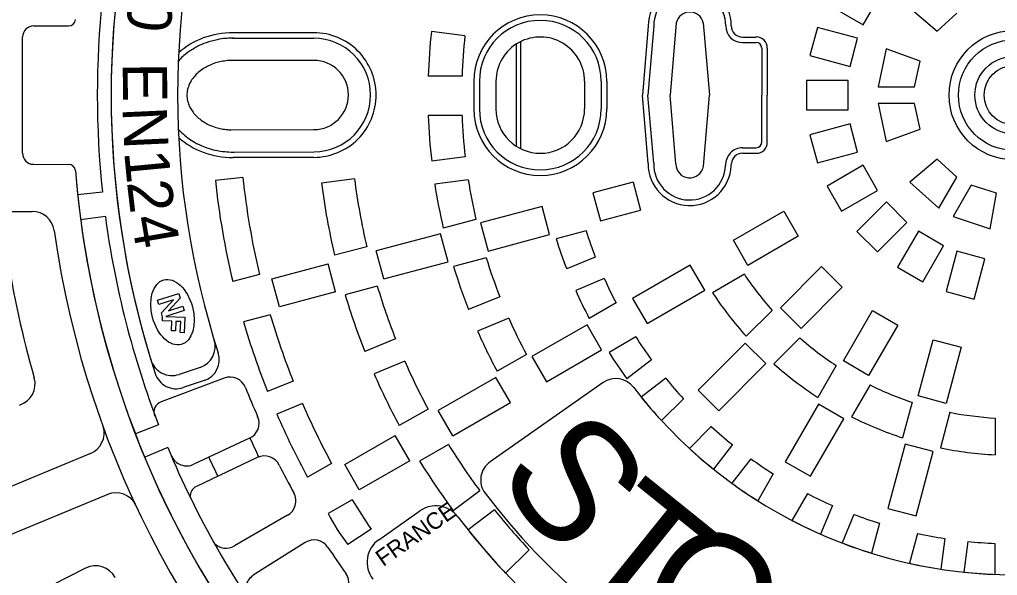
# Model space of a CAD drawing. Extents: x -7.1 to 10, y -5 to 6.
# Drawn here: x -5.508 to -4.588, y 0.27 to 0.793 of the extents above; entities that cross this region are included whole.
import ezdxf

# ---------------------------------------------------------------- set-up
doc = ezdxf.new("R2010")
doc.units = 0
doc.layers.add('Level 1', color=7, linetype='Continuous')

# ---------------------------------------------------------------- blocks, each defined once
blk = doc.blocks.new('CRAN')
at = {"layer": 'Level 1'}
for p, q in [((-3.652, 6.599), (-1.391, 7.083)), ((-3.232, 4.178), (-1.568, 4.4)), ((-1.568, 4.4), (-1.47, 3.52)), ((-3.114, 3.352), (-1.47, 3.52)), ((-2.949, 0.9), (-0.638, 0.965)), ((-2.949, -0.892), (-0.638, -0.957)), ((-3.114, -3.345), (-1.471, -3.52)), ((-1.568, -4.392), (-1.47, -3.512)), ((-3.232, -4.17), (-1.568, -4.392)), ((-3.652, -6.592), (-1.391, -7.076))]:
    blk.add_line(p, q, dxfattribs=at)
for centre, radius, start, end in [((-1.26, 6.472), 0.625, 11.0144, 102.0722), ((-3.521, 5.988), 0.625, 102.0722, 190.9368), ((-34.491, 0.004), 30.918, 8.7409, 10.9368), ((-3.315, 4.797), 0.625, 188.7409, 277.6056), ((-3.048, 2.731), 0.625, 96.0776, 184.9422), ((-34.473, 0.013), 30.918, 2.7463, 4.9422), ((-2.967, 1.524), 0.625, 182.7463, 271.611), ((-0.656, 1.589), 0.625, 271.611, 348.8242), ((-2.967, -1.517), 0.625, 88.389, 177.2537), ((-0.656, -1.582), 0.625, 11.1758, 88.389), ((-34.473, -0.006), 30.918, 355.0578, 357.2537), ((-3.048, -2.723), 0.625, 175.0578, 263.9224), ((-3.315, -4.79), 0.625, 82.3944, 171.2591), ((-34.491, 0.004), 30.918, 349.0632, 351.2591), ((-3.521, -5.981), 0.625, 169.0632, 257.9278), ((-1.26, -6.464), 0.625, 257.9278, 348.9856)]:
    blk.add_arc(centre, radius, start, end, dxfattribs=at)

msp = doc.modelspace()

# ---------------------------------------------------------------- linework, layer by layer
at = {"layer": 'Level 1'}
for p, q in [((-4.71412, 0.78776), (-4.70045, 0.81144)), ((-4.74806, 0.80735), (-4.71412, 0.78776)), ((-4.67027, 0.80377), (-4.64433, 0.78201)), ((-4.64433, 0.78201), (-4.62597, 0.79878)), ((-5.49433, 0.78688), (-5.46154, 0.78688)), ((-4.91624, 0.78688), (-4.92173, 0.72178)), ((-4.91103, 0.78688), (-4.9165, 0.72178)), ((-4.88986, 0.78985), (-4.8956, 0.72178)), ((-4.8645, 0.78985), (-4.85876, 0.72178)), ((-4.75715, 0.78541), (-4.76422, 0.759)), ((-4.7193, 0.77527), (-4.75715, 0.78541)), ((-5.50484, 0.66714), (-5.50475, 0.77647)), ((-5.3072, 0.77531), (-5.23079, 0.77531)), ((-5.23079, 0.78052), (-5.3068, 0.78052)), ((-5.08867, 0.77761), (-5.12018, 0.78176)), ((-4.8277, 0.77646), (-4.81468, 0.77646)), ((-4.72638, 0.74886), (-4.7193, 0.77527)), ((-5.04044, 0.76976), (-5.04044, 0.67446)), ((-5.03653, 0.77038), (-5.03653, 0.67154)), ((-4.8277, 0.77126), (-4.81468, 0.77126)), ((-4.80947, 0.76605), (-4.80947, 0.72178)), ((-4.80426, 0.76605), (-4.80426, 0.72178)), ((-4.69238, 0.76546), (-4.69986, 0.72959)), ((-4.66058, 0.75387), (-4.69238, 0.76546)), ((-5.23079, 0.75448), (-5.3068, 0.75447)), ((-4.76422, 0.759), (-4.72638, 0.74886)), ((-4.66592, 0.72959), (-4.66058, 0.75387)), ((-5.09137, 0.7397), (-5.12316, 0.73977)), ((-5.0803, 0.7348), (-5.0803, 0.70876)), ((-5.0751, 0.7348), (-5.0751, 0.70876)), ((-5.05947, 0.7348), (-5.05947, 0.70876)), ((-4.97614, 0.7348), (-4.97614, 0.70876)), ((-4.96051, 0.7348), (-4.96051, 0.70876)), ((-4.9553, 0.7348), (-4.9553, 0.70876)), ((-4.76732, 0.73545), (-4.76732, 0.70811)), ((-4.72814, 0.73545), (-4.76732, 0.73545)), ((-4.72814, 0.70811), (-4.72814, 0.73545)), ((-4.69986, 0.72959), (-4.66592, 0.72959)), ((-4.91631, 0.65751), (-4.92173, 0.72178)), ((-4.9111, 0.65768), (-4.9165, 0.72178)), ((-4.89027, 0.65718), (-4.8956, 0.72178)), ((-4.86439, 0.65496), (-4.85876, 0.72178)), ((-4.80947, 0.67751), (-4.80947, 0.72178)), ((-4.80426, 0.67751), (-4.80426, 0.72178)), ((-4.66592, 0.71396), (-4.69986, 0.71396)), ((-4.69986, 0.71396), (-4.69238, 0.67809)), ((-4.66058, 0.68968), (-4.66592, 0.71396)), ((-5.09133, 0.70249), (-5.12312, 0.70249)), ((-4.76732, 0.70811), (-4.72814, 0.70811)), ((-4.72638, 0.6947), (-4.76422, 0.68456)), ((-4.7193, 0.66829), (-4.72638, 0.6947)), ((-5.30842, 0.6891), (-5.23068, 0.68937)), ((-4.76422, 0.68456), (-4.75715, 0.65814)), ((-4.69238, 0.67809), (-4.66058, 0.68968)), ((-4.82766, 0.6723), (-4.81468, 0.6723)), ((-5.3072, 0.66825), (-5.23059, 0.66854)), ((-5.23079, 0.66304), (-5.3068, 0.66304)), ((-5.08844, 0.66379), (-5.11994, 0.65964)), ((-4.82766, 0.66709), (-4.81468, 0.66709)), ((-4.75715, 0.65814), (-4.7193, 0.66829)), ((-5.49443, 0.65672), (-5.46153, 0.65668)), ((-4.83822, 0.65541), (-4.83804, 0.65755)), ((-4.71412, 0.65579), (-4.74806, 0.6362)), ((-4.70045, 0.63211), (-4.71412, 0.65579)), ((-4.64433, 0.66154), (-4.67027, 0.63979)), ((-4.62597, 0.64478), (-4.64433, 0.66154)), ((-5.29754, 0.64437), (-5.32343, 0.6416)), ((-4.64294, 0.61538), (-4.62597, 0.64478)), ((-5.19251, 0.64305), (-5.22351, 0.63911)), ((-5.08553, 0.64211), (-5.11704, 0.63796)), ((-4.93048, 0.64001), (-4.96821, 0.6299)), ((-4.93048, 0.64001), (-4.92341, 0.6136)), ((-4.74806, 0.6362), (-4.73439, 0.61252)), ((-4.67027, 0.63979), (-4.64294, 0.61538)), ((-4.61244, 0.63696), (-4.62941, 0.60757)), ((-4.58874, 0.62945), (-4.61244, 0.63696)), ((-5.42962, 0.63051), (-5.45293, 0.62803)), ((-4.96821, 0.6299), (-4.96114, 0.60349)), ((-4.73439, 0.61252), (-4.70045, 0.63211)), ((-4.59461, 0.5961), (-4.58874, 0.62945)), ((-5.01603, 0.61709), (-5.07391, 0.60158)), ((-5.00896, 0.59067), (-5.01603, 0.61709)), ((-4.69222, 0.62138), (-4.71993, 0.59368)), ((-4.67289, 0.60205), (-4.69222, 0.62138)), ((-5.56204, 0.61237), (-5.49564, 0.61237)), ((-5.42689, 0.60769), (-5.45012, 0.60459)), ((-4.96114, 0.60349), (-4.92341, 0.6136)), ((-4.83616, 0.58534), (-4.78873, 0.61272)), ((-4.78873, 0.61272), (-4.77506, 0.58904)), ((-4.62941, 0.60757), (-4.59461, 0.5961)), ((-5.07833, 0.60479), (-5.10905, 0.59663)), ((-5.07391, 0.60158), (-5.06683, 0.57516)), ((-4.70059, 0.57434), (-4.67289, 0.60205)), ((-5.11165, 0.59146), (-5.17204, 0.57528)), ((-5.11165, 0.59146), (-5.17204, 0.57528)), ((-5.10458, 0.56505), (-5.11165, 0.59146)), ((-5.06683, 0.57516), (-5.00896, 0.59067)), ((-4.97468, 0.59405), (-5.00281, 0.58651)), ((-4.77506, 0.58904), (-4.82248, 0.56166)), ((-4.71993, 0.59368), (-4.70059, 0.57434)), ((-4.66216, 0.59382), (-4.68175, 0.55988)), ((-4.63848, 0.58014), (-4.66216, 0.59382)), ((-4.82248, 0.56166), (-4.83616, 0.58534)), ((-4.65807, 0.54621), (-4.63848, 0.58014)), ((-5.18099, 0.57912), (-5.21126, 0.57132)), ((-5.16496, 0.54887), (-5.17204, 0.57528)), ((-4.62598, 0.57497), (-4.63612, 0.53712)), ((-4.59957, 0.56789), (-4.62598, 0.57497)), ((-5.27016, 0.54899), (-5.21733, 0.56315)), ((-5.21025, 0.53674), (-5.21733, 0.56315)), ((-5.16496, 0.54887), (-5.10458, 0.56505)), ((-5.06866, 0.56887), (-5.09936, 0.56064)), ((-4.96601, 0.56944), (-4.99291, 0.5583)), ((-4.87679, 0.56188), (-4.93095, 0.53061)), ((-4.86312, 0.5382), (-4.87679, 0.56188)), ((-4.60971, 0.53004), (-4.59957, 0.56789)), ((-5.28188, 0.5531), (-5.3071, 0.54659)), ((-4.8258, 0.55326), (-4.85577, 0.53596)), ((-4.79186, 0.52175), (-4.75314, 0.56047)), ((-4.75314, 0.56047), (-4.7338, 0.54113)), ((-4.68175, 0.55988), (-4.65807, 0.54621)), ((-5.26309, 0.52258), (-5.27016, 0.54899)), ((-4.95759, 0.54925), (-4.98449, 0.53811)), ((-5.37783, 0.52889), (-5.35782, 0.53514)), ((-5.35782, 0.53514), (-5.35643, 0.53072)), ((-5.21025, 0.53674), (-5.26309, 0.52258)), ((-5.17107, 0.54196), (-5.20129, 0.53395)), ((-4.91728, 0.50693), (-4.86312, 0.5382)), ((-4.7338, 0.54113), (-4.77252, 0.50241)), ((-4.63612, 0.53712), (-4.60971, 0.53004)), ((-5.37662, 0.52485), (-5.37783, 0.52889)), ((-5.36265, 0.52931), (-5.37662, 0.52485)), ((-5.37415, 0.51716), (-5.36265, 0.52931)), ((-5.35643, 0.53072), (-5.36761, 0.51894)), ((-5.05585, 0.53223), (-5.0852, 0.52007)), ((-4.94648, 0.52632), (-4.97173, 0.51181)), ((-4.93095, 0.53061), (-4.91728, 0.50693)), ((-5.37301, 0.51336), (-5.37415, 0.51716)), ((-5.35282, 0.51915), (-5.3701, 0.51373)), ((-5.36761, 0.51894), (-5.35403, 0.52322)), ((-5.35403, 0.52322), (-5.35282, 0.51915)), ((-5.27179, 0.51524), (-5.29698, 0.50856)), ((-4.79963, 0.51936), (-4.82413, 0.49495)), ((-4.77252, 0.50241), (-4.79186, 0.52175)), ((-4.73261, 0.47178), (-4.70523, 0.51921)), ((-4.70523, 0.51921), (-4.68155, 0.50554)), ((-5.37322, 0.50956), (-5.37301, 0.51336)), ((-5.36431, 0.50918), (-5.37322, 0.50956)), ((-5.3701, 0.51373), (-5.35206, 0.51292)), ((-5.36466, 0.50006), (-5.36431, 0.50918)), ((-5.36055, 0.509), (-5.36099, 0.49995)), ((-5.35584, 0.50878), (-5.36055, 0.509)), ((-5.35636, 0.49841), (-5.35584, 0.50878)), ((-5.35206, 0.51292), (-5.35276, 0.49821)), ((-5.04743, 0.51204), (-5.07679, 0.49988)), ((-5.36099, 0.49995), (-5.36466, 0.50006)), ((-5.35276, 0.49821), (-5.35636, 0.49841)), ((-4.97382, 0.50586), (-5.02571, 0.4759)), ((-4.96015, 0.48218), (-4.97382, 0.50586)), ((-4.68155, 0.50554), (-4.70893, 0.45811)), ((-5.15389, 0.49243), (-5.18281, 0.48057)), ((-4.92791, 0.49431), (-4.95314, 0.47974)), ((-4.82503, 0.48857), (-4.86926, 0.44435)), ((-4.8057, 0.46923), (-4.82503, 0.48857)), ((-4.77356, 0.49344), (-4.79802, 0.46897)), ((-4.66245, 0.43886), (-4.64828, 0.49175)), ((-4.64828, 0.49175), (-4.62187, 0.48468)), ((-5.01204, 0.45222), (-4.96015, 0.48218)), ((-4.62187, 0.48468), (-4.63604, 0.43178)), ((-5.1452, 0.47152), (-5.17407, 0.45955)), ((-5.03082, 0.47786), (-5.05838, 0.46202)), ((-5.02571, 0.4759), (-5.01204, 0.45222)), ((-4.91318, 0.47278), (-4.93627, 0.45506)), ((-4.84992, 0.42501), (-4.8057, 0.46923)), ((-4.70893, 0.45811), (-4.73261, 0.47178)), ((-5.33783, 0.46576), (-5.3576, 0.45915)), ((-4.7395, 0.46747), (-4.75685, 0.43755)), ((-5.31511, 0.45566), (-5.37444, 0.4334)), ((-5.33392, 0.45333), (-5.35368, 0.44673)), ((-5.25027, 0.4529), (-5.27437, 0.44302)), ((-5.05955, 0.45636), (-5.1137, 0.4251)), ((-5.05955, 0.45636), (-5.1137, 0.4251)), ((-4.95868, 0.45136), (-5.06497, 0.37694)), ((-5.04588, 0.43268), (-5.05955, 0.45636)), ((-4.89982, 0.45546), (-4.92291, 0.43774)), ((-4.86926, 0.44435), (-4.84992, 0.42501)), ((-4.70761, 0.44918), (-4.72491, 0.41922)), ((-5.10002, 0.40142), (-5.04588, 0.43268)), ((-4.88314, 0.43619), (-4.90378, 0.41564)), ((-4.66799, 0.43291), (-4.67701, 0.39952)), ((-4.63604, 0.43178), (-4.66245, 0.43886)), ((-5.24145, 0.43164), (-5.26551, 0.42167)), ((-5.12334, 0.42649), (-5.15055, 0.41112)), ((-5.10002, 0.40142), (-5.1137, 0.4251)), ((-4.75607, 0.43115), (-4.78734, 0.37699)), ((-4.73239, 0.41748), (-4.75607, 0.43115)), ((-4.63245, 0.4235), (-4.6414, 0.39008)), ((-4.76366, 0.36332), (-4.73239, 0.41748)), ((-4.58997, 0.41803), (-4.59004, 0.38345)), ((-5.3768, 0.41178), (-5.39867, 0.40335)), ((-4.85693, 0.41007), (-4.87752, 0.38947)), ((-5.2913, 0.39901), (-5.34367, 0.37455)), ((-5.20167, 0.37431), (-5.1543, 0.40166)), ((-5.14063, 0.37798), (-5.1543, 0.40166)), ((-5.36825, 0.39045), (-5.38988, 0.38144)), ((-5.10413, 0.39317), (-5.13125, 0.3776)), ((-4.83712, 0.39309), (-4.85484, 0.37)), ((-4.6746, 0.39354), (-4.69078, 0.33313)), ((-4.64818, 0.38646), (-4.6746, 0.39354)), ((-4.66437, 0.32605), (-4.64818, 0.38646)), ((-5.4409, 0.38465), (-5.57518, 0.32903)), ((-5.28403, 0.38101), (-5.34123, 0.35375)), ((-5.14063, 0.37798), (-5.188, 0.35063)), ((-4.81974, 0.37982), (-4.83746, 0.35672)), ((-5.21405, 0.37524), (-5.23673, 0.36243)), ((-5.188, 0.35063), (-5.20167, 0.37431)), ((-4.78734, 0.37699), (-4.76366, 0.36332)), ((-4.79864, 0.36552), (-4.81326, 0.34033)), ((-5.07472, 0.34977), (-5.09958, 0.33083)), ((-5.42378, 0.34664), (-5.55923, 0.29053)), ((-5.19483, 0.34128), (-5.21742, 0.32831)), ((-4.76656, 0.34707), (-4.78112, 0.32185)), ((-5.06091, 0.33182), (-5.08571, 0.31279)), ((-4.74304, 0.3358), (-4.75418, 0.3089)), ((-4.69078, 0.33313), (-4.66437, 0.32605)), ((-5.25546, 0.32661), (-5.30554, 0.29776)), ((-5.1696, 0.30367), (-5.13098, 0.33072)), ((-4.7228, 0.32748), (-4.73395, 0.30058)), ((-5.17697, 0.31352), (-5.19868, 0.29914)), ((-4.69873, 0.31912), (-4.70633, 0.29101)), ((-4.66297, 0.30961), (-4.6705, 0.28147)), ((-4.63733, 0.30481), (-4.64113, 0.27595)), ((-4.61563, 0.30201), (-4.61943, 0.27315)), ((-4.59021, 0.30017), (-4.59027, 0.27105)), ((-5.02814, 0.29398), (-5.05045, 0.27209)), ((-5.44548, 0.27685), (-5.49287, 0.25286))]:
    msp.add_line(p, q, dxfattribs=at)
for radius in [0.0608, 0.05199, 0.03649, 0.02784]:
    msp.add_circle((-4.57249, 0.72178), radius, dxfattribs=at)
for centre, radius, start, end in [((-4.57265, 0.72181), 1.15162, 195.07169, 189.12267), ((-4.57249, 0.72178), 0.84896, 162.04053, 197.95947), ((-4.57249, 0.72178), 0.84896, 162.94156, 197.05844), ((-4.57249, 0.72178), 0.78646, 162.05448, 197.94552), ((-4.87718, 0.78688), 0.03906, 0, 180), ((-4.87718, 0.78688), 0.03385, 0, 180), ((-4.57249, 0.72178), 0.86198, 173.92199, 186.07801), ((-5.46154, 0.79339), 0.00651, 270, 355.39465), ((-4.57292, 0.7213), 0.88503, 175.36183, 175.36231), ((-5.0178, 0.7348), 0.0625, 0, 180), ((-5.0178, 0.7348), 0.05729, 0, 180), ((-4.87718, 0.78688), 0.01302, 13.17501, 166.82499), ((-5.49433, 0.77646), 0.01042, 90, 179.95159), ((-4.8277, 0.78688), 0.01563, 180, 270), ((-4.8277, 0.78688), 0.01042, 180, 270), ((-5.23079, 0.72192), 0.05859, 359.85765, 90), ((-5.23079, 0.72192), 0.05339, 270.21624, 90.00157), ((-4.57249, 0.72178), 0.55096, 173.75013, 178.12895), ((-4.57249, 0.72178), 0.51919, 173.82664, 178.02167), ((-5.0178, 0.7348), 0.04167, 0, 118.64641), ((-5.03393, 0.77038), 0.0026, 114.37684, 180), ((-4.81468, 0.76605), 0.01042, 0, 90), ((-5.0178, 0.7348), 0.04167, 118.64641, 180), ((-4.81468, 0.76605), 0.00521, 0, 90), ((-5.23079, 0.72192), 0.03255, 270.19643, 90.00229), ((-5.23079, 0.72186), 0.05859, 270.1038, 0.24616), ((-5.0178, 0.70876), 0.0625, 180, 0), ((-5.0178, 0.70876), 0.05729, 180, 0), ((-5.0178, 0.70876), 0.04167, 180, 0), ((-4.57249, 0.72178), 0.55096, 182.00587, 186.47515), ((-4.57249, 0.72178), 0.51919, 182.12867, 186.41243), ((-4.82756, 0.65641), 0.01588, 90.3638, 182.83734), ((-4.81468, 0.67751), 0.00521, 270, 0), ((-4.81468, 0.67751), 0.01042, 270, 0), ((-5.49442, 0.66714), 0.01042, 179.95159, 269.92873), ((-4.82766, 0.65667), 0.01042, 90, 175.17942), ((-5.46154, 0.65017), 0.00651, 4.60506, 89.92873), ((-4.87725, 0.65702), 0.03906, 179.28321, 357.6488), ((-4.87725, 0.65702), 0.03385, 178.87213, 357.6488), ((-4.87725, 0.65702), 0.01302, 179.28321, 350.90166), ((-4.57292, 0.7213), 0.88503, 184.51287, 184.57671), ((-4.57249, 0.72178), 0.88542, 184.60506, 245.30477), ((-4.57249, 0.72178), 0.88542, 184.60506, 354.33256), ((-4.57249, 0.72178), 0.72917, 186.09418, 193.3753), ((-4.57249, 0.72178), 0.75521, 186.09418, 193.41284), ((-4.57249, 0.72178), 0.65625, 187.23641, 193.25436), ((-4.57249, 0.72178), 0.625, 187.23641, 193.19389), ((-4.57249, 0.72178), 0.55096, 188.75013, 193.12895), ((-4.57249, 0.72178), 0.51919, 188.82664, 193.02167), ((-5.49564, 0.59154), 0.02083, 8.03047, 90.00167), ((-4.57249, 0.72178), 0.86198, 187.60558, 201.07801), ((-4.57249, 0.72178), 0.91146, 188.03047, 347.68481), ((-4.57249, 0.72178), 0.42198, 197.61937, 201.16184), ((-4.57249, 0.72178), 0.45108, 197.45028, 201.24818), ((-4.56744, 0.72116), 0.96354, 188.79178, 195.97618), ((-4.57249, 0.72178), 0.51919, 197.12867, 201.41243), ((-4.57249, 0.72178), 0.55096, 197.00587, 201.47515), ((-4.57249, 0.72178), 0.30425, 213.63416, 221.70655), ((-4.57249, 0.72178), 0.42198, 204.13234, 207.59298), ((-4.57249, 0.72178), 0.65625, 196.63169, 201.56459), ((-4.57249, 0.72178), 0.625, 196.72031, 201.52788), ((-4.57249, 0.72178), 0.45108, 204.02701, 207.74069), ((-4.57249, 0.72178), 0.33878, 213.26326, 222.03051), ((-4.57249, 0.72178), 0.72917, 196.45447, 201.63801), ((-4.57249, 0.72178), 0.75521, 196.39947, 201.6608), ((-4.57249, 0.72178), 0.51919, 203.82664, 208.02167), ((-4.57249, 0.72178), 0.55096, 203.75013, 208.12895), ((-5.34444, 0.48551), 0.02083, 288.49444, 17.01567), ((-4.57249, 0.72178), 0.42198, 212.61937, 216.16184), ((-4.57249, 0.72178), 0.30425, 228.63416, 236.70655), ((-5.34053, 0.47309), 0.02083, 288.49444, 17.93996), ((-4.57249, 0.72178), 0.45108, 212.45028, 216.24818), ((-5.36421, 0.4789), 0.02083, 197.05288, 288.49444), ((-4.57249, 0.72178), 0.625, 203.60431, 208.19389), ((-5.36029, 0.46648), 0.02083, 197.95391, 288.49444), ((-4.57249, 0.72178), 0.33878, 228.26326, 237.03051), ((-5.5138, 0.45022), 0.02083, 287.34619, 15.97618), ((-5.30962, 0.44103), 0.01562, 21.70397, 110.56861), ((-4.57249, 0.72178), 0.65625, 203.55203, 208.25436), ((-4.94673, 0.4343), 0.02083, 37.53023, 125), ((-4.57249, 0.72178), 0.42198, 219.13234, 222.59298), ((-4.57696, 0.73265), 0.77294, 201.70397, 203.89985), ((-4.57249, 0.72178), 0.45108, 217.53023, 322.46977), ((-4.57249, 0.72178), 0.30425, 243.63416, 251.70655), ((-5.37078, 0.42364), 0.01042, 110.56861, 201.27812), ((-4.57249, 0.72178), 0.45108, 219.02701, 222.74069), ((-4.57249, 0.72178), 0.72917, 203.44749, 208.3753), ((-4.57249, 0.72178), 0.30425, 258.63416, 266.70655), ((-5.29791, 0.41317), 0.01562, 295.03521, 23.89985), ((-4.57249, 0.72178), 0.75521, 203.41505, 208.41284), ((-4.57249, 0.72178), 0.33878, 243.26326, 252.03051), ((-5.44888, 0.4039), 0.02083, 292.50167, 16.62284), ((-4.57249, 0.72178), 0.42198, 227.61937, 231.16184), ((-4.57249, 0.72178), 0.78745, 204.1803, 205.59091), ((-4.57249, 0.72178), 0.86198, 202.60558, 216.73442), ((-4.57249, 0.72178), 0.625, 211.72031, 216.52788), ((-4.57249, 0.72178), 0.45108, 227.45028, 231.24818), ((-4.57249, 0.72178), 0.33878, 258.26326, 267.03051), ((-5.35028, 0.38871), 0.01562, 203.97738, 295.03521), ((-4.57249, 0.72178), 0.83011, 204.22478, 205.58518), ((-5.27731, 0.3669), 0.01562, 26.61094, 115.47558), ((-4.57249, 0.72178), 0.65625, 211.63169, 216.56459), ((-4.57249, 0.72178), 0.42198, 234.13234, 237.59298), ((-4.57228, 0.72012), 0.77294, 206.61094, 208.80682), ((-5.05302, 0.35988), 0.02083, 125, 216.98467), ((-5.33675, 0.34435), 0.01042, 115.47558, 183.37664), ((-4.57249, 0.72178), 0.45108, 234.02701, 237.74069), ((-5.417, 0.32694), 0.02083, 25.13489, 112.50167), ((-5.26325, 0.34015), 0.01562, 299.94218, 28.80682), ((-4.57281, 0.72178), 0.72917, 211.45447, 214.04821), ((-4.57249, 0.72178), 0.6224, 216.98467, 323.01533), ((-4.57249, 0.72178), 0.42198, 242.61937, 246.16184), ((-5.11605, 0.30938), 0.02604, 37.18739, 125), ((-4.57249, 0.72178), 0.625, 218.60431, 223.19389), ((-5.07946, 0.39633), 0.15381, 206.24345, 219.18615), ((-4.57249, 0.72178), 0.65625, 217.18739, 322.81261), ((-4.57249, 0.72178), 0.42198, 249.13234, 252.59298), ((-4.57249, 0.72178), 0.65625, 218.55203, 223.25436), ((-4.57249, 0.72178), 0.45108, 242.45028, 246.24818), ((-5.15467, 0.28234), 0.02604, 125, 217.09037), ((-4.57249, 0.72178), 0.42198, 257.61937, 261.16184), ((-5.31334, 0.3113), 0.01562, 225.24421, 299.94218), ((-4.57249, 0.72178), 0.45108, 249.02701, 252.74069), ((-4.57249, 0.72178), 0.42198, 264.13234, 267.59298), ((-5.43607, 0.25827), 0.02083, 28.06106, 116.85647), ((-4.57249, 0.72178), 0.45108, 257.45028, 261.24818), ((-4.57117, 0.7239), 1.09834, 204.31426, 222.86536), ((-4.57249, 0.72178), 0.45108, 264.02701, 267.74069)]:
    msp.add_arc(centre, radius, start, end, dxfattribs=at)
for start_param, end_param in [(4.712389, 5.541257), (0.741928, 1.570796)]:
    msp.add_ellipse((-5.3068, 0.72178), major_axis=(-0.06939, 0), ratio=0.846565, start_param=start_param, end_param=end_param, dxfattribs=at)
msp.add_ellipse((-5.36371, 0.51764), major_axis=(-0.00823, 0.03039), ratio=0.617254, dxfattribs=at)
for points in [[(-5.30642, 0.77531), (-5.30683, 0.77531), (-5.30725, 0.77531), (-5.31421, 0.77523), (-5.32074, 0.77431), (-5.33314, 0.77088), (-5.33902, 0.76837), (-5.34958, 0.76203), (-5.35425, 0.75819), (-5.35818, 0.75382), (-5.35824, 0.75375), (-5.3583, 0.75369)], [(-5.3068, 0.75447), (-5.30916, 0.75447), (-5.31152, 0.75433), (-5.31828, 0.75346), (-5.32259, 0.75236), (-5.33046, 0.74925), (-5.33403, 0.74726), (-5.34012, 0.74273), (-5.34263, 0.74019), (-5.34655, 0.73495), (-5.34795, 0.73225), (-5.34973, 0.72695), (-5.35014, 0.72436), (-5.35014, 0.72178), (-5.35014, 0.71911), (-5.3497, 0.71644), (-5.34783, 0.71106), (-5.3464, 0.70836), (-5.34242, 0.70313), (-5.33987, 0.7006), (-5.33372, 0.69611), (-5.33013, 0.69413), (-5.32221, 0.69109), (-5.31789, 0.69001), (-5.31178, 0.68928), (-5.3101, 0.68915), (-5.30842, 0.6891)], [(-5.3583, 0.68987), (-5.35638, 0.68772), (-5.35427, 0.68568), (-5.34737, 0.67997), (-5.34205, 0.67673), (-5.33047, 0.67173), (-5.3242, 0.66997), (-5.31381, 0.66846), (-5.30981, 0.6682), (-5.30581, 0.66825)]]:
    msp.add_open_spline(points, degree=3, dxfattribs=at)

# ---------------------------------------------------------------- block references
at = {"layer": 'Level 1', "xscale": 0.025, "yscale": 0.024999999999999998, "rotation": -135.66}
msp.add_blockref('CRAN', (-5.18898, 0.11933), dxfattribs=at)

# ---------------------------------------------------------------- texts
at = {"layer": 'Level 1'}
for s, height, rotation, p in [('0', 0.04167, 263.15837, (-5.40403, 0.81488)), ('E', 0.04167, 270.5, (-5.41056, 0.75221)), ('N', 0.04167, 272.59621, (-5.41084, 0.71017)), ('1', 0.04167, 275.42738, (-5.40923, 0.66849)), ('2', 0.04167, 276.68722, (-5.4066, 0.64001)), ('4', 0.04167, 279.79802, (-5.40295, 0.6062)), ('S', 0.11437, 309.03342, (-5.06171, 0.36363)), ('T', 0.11438, 321.15595, (-4.99321, 0.27729)), ('FRANCE', 0.015625, 35.12775, (-5.16559, 0.27792)), ('O', 0.11438, 329.10803, (-4.93644, 0.2332))]:
    msp.add_text(s, height=height, rotation=rotation, dxfattribs=at).set_placement(p)

doc.saveas('drawing.dxf')
